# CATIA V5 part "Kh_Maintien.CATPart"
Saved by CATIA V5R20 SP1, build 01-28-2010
Part number: Maintien
Bounding box of the stored display mesh (mm): x -31.991 to 31.991, y -32 to 32, z 0 to 7
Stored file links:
  G:\Khaled_CFAO_2011\SIL\SIL_GR1\tmerino\Khaled\CAD_Thinkmotion\Kh_Maintien.CATPart
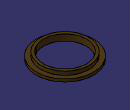
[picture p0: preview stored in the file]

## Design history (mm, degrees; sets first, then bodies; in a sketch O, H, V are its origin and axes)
Body1 (main body)
  Sketch1 on yz-plane, origin (0, 0, 0), H (0, 1, 0), V (0, 0, 1)
    line L1 (24, 7) -> (24, 0)
    line L2 (24, 0) -> (32, 0)
    line L3 (32, 0) -> (32, 3)
    line L4 (32, 3) -> (27, 3)
    line L5 (27, 3) -> (27, 7)
    line L6 (27, 7) -> (24, 7)
    distance V L1 = 24
    distance L1 L5 = 3
    distance L1 L3 = 8
    distance L6 L4 = 4
    distance L4 L2 = 3
    vertical: L1 V, L3 V, L5 V
    horizontal: L2 H, L4 H, L6 H
  Shaft1: profile Sketch1, axis Sketch1.V, angle 360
